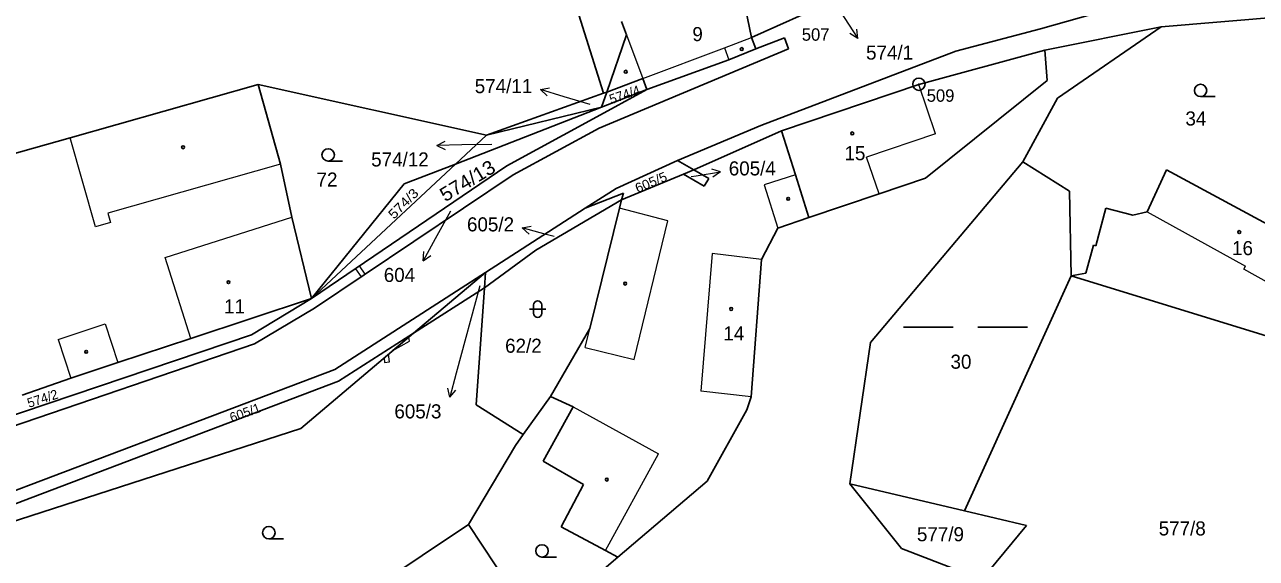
# Model space of a CAD drawing. Extents: x -664548 to -662415, y -1069720 to -1068208.
# Drawn here: x -663758.5 to -663609.5, y -1068970.2 to -1068905.8 of the extents above; entities that cross this region are included whole.
import ezdxf
from ezdxf.enums import TextEntityAlignment as Align

# ---------------------------------------------------------------- set-up
doc = ezdxf.new("R2010")
doc.units = 0
doc.header["$LTSCALE"] = 0.68
for name, color, linetype, lineweight in [('1', 7, 'Continuous', 25), ('13', 7, 'Continuous', 13), ('3', 7, 'Continuous', 25), ('4', 7, 'Continuous', 13), ('5', 7, 'Continuous', 25), ('7', 7, 'Continuous', 13), ('8', 7, 'Continuous', 25)]:
    doc.layers.add(name, color=color, linetype=linetype, lineweight=lineweight)
doc.layers.add('2', color=7, linetype='Continuous')

msp = doc.modelspace()

# ---------------------------------------------------------------- linework, layer by layer
at = {"layer": '1'}
for p, q in [((-663688.48, -1068914.05), (-663694.97, -1068893.3)), ((-663670.58, -1068907.33), (-663672.05, -1068900.05)), ((-663661.03, -1068903.04), (-663670.58, -1068907.33)), ((-663635.63, -1068906.27), (-663624.91, -1068903.24)), ((-663686.3, -1068905.38), (-663685.7, -1068906.99)), ((-663621.07, -1068906.02), (-663605.87, -1068904.77)), ((-663688.09, -1068913.91), (-663685.7, -1068906.99)), ((-663645.87, -1068908.98), (-663635.63, -1068906.27)), ((-663635.13, -1068908.83), (-663621.07, -1068906.02)), ((-663633.59, -1068914.64), (-663621.07, -1068906.02)), ((-663670.58, -1068907.33), (-663670.07, -1068908.7)), ((-663666.61, -1068907.36), (-663670.07, -1068908.7)), ((-663666.12, -1068908.69), (-663666.61, -1068907.36)), ((-663666.12, -1068908.69), (-663688.99, -1068918.26)), ((-663673.32, -1068910.01), (-663683.22, -1068913.6)), ((-663670.07, -1068908.7), (-663673.32, -1068910.01)), ((-663669.47, -1068917.93), (-663645.87, -1068908.98)), ((-663650.34, -1068913.01), (-663635.13, -1068908.83)), ((-663634.85, -1068912.51), (-663635.13, -1068908.83)), ((-663752.94, -1068919.42), (-663730.23, -1068912.99)), ((-663727.51, -1068922.61), (-663730.23, -1068912.99)), ((-663730.23, -1068912.99), (-663702.63, -1068919.1)), ((-663688.09, -1068913.91), (-663683.73, -1068912.25)), ((-663683.22, -1068913.6), (-663683.73, -1068912.25)), ((-663650.34, -1068913.01), (-663666.94, -1068918.58)), ((-663634.85, -1068912.51), (-663649.56, -1068924.31)), ((-663702.63, -1068919.1), (-663688.48, -1068914.05)), ((-663689.73, -1068917.14), (-663683.22, -1068913.6)), ((-663683.22, -1068913.6), (-663688.72, -1068915.74)), ((-663688.72, -1068915.74), (-663688.09, -1068913.91)), ((-663688.48, -1068914.05), (-663688.09, -1068913.91)), ((-663688.72, -1068915.74), (-663706.38, -1068922.6)), ((-663688.72, -1068915.74), (-663702.63, -1068919.1)), ((-663637.77, -1068922.34), (-663633.59, -1068914.64)), ((-663700.15, -1068922.8), (-663689.73, -1068917.14)), ((-663688.99, -1068918.26), (-663699.4, -1068923.92)), ((-663679.51, -1068922.17), (-663669.47, -1068917.93)), ((-663677.57, -1068923.28), (-663666.94, -1068918.58)), ((-663666.94, -1068918.58), (-663665.25, -1068923.92)), ((-663762.84, -1068922.22), (-663752.94, -1068919.42)), ((-663706.38, -1068922.6), (-663702.63, -1068919.1)), ((-663726.17, -1068929.03), (-663727.51, -1068922.61)), ((-663723.79, -1068938.86), (-663706.38, -1068922.6)), ((-663723.79, -1068938.86), (-663700.15, -1068922.8)), ((-663712.56, -1068925), (-663706.38, -1068922.6)), ((-663686.95, -1068925.55), (-663679.51, -1068922.17)), ((-663677.57, -1068923.28), (-663679.51, -1068922.17)), ((-663678.82, -1068923.83), (-663677.57, -1068923.28)), ((-663675.74, -1068924.33), (-663677.57, -1068923.28)), ((-663656.19, -1068944.16), (-663637.77, -1068922.34)), ((-663637.77, -1068922.34), (-663632.15, -1068925.87)), ((-663620.39, -1068923.28), (-663622.73, -1068928.37)), ((-663600.3, -1068934.16), (-663620.39, -1068923.28)), ((-663712.56, -1068925), (-663723.79, -1068938.86)), ((-663699.4, -1068923.92), (-663723.41, -1068940)), ((-663686.29, -1068926.91), (-663678.82, -1068923.83)), ((-663676.31, -1068925.27), (-663678.82, -1068923.83)), ((-663675.74, -1068924.33), (-663676.31, -1068925.27)), ((-663665.25, -1068923.92), (-663663.63, -1068929.07)), ((-663649.56, -1068924.31), (-663655.16, -1068926.21)), ((-663686.95, -1068925.55), (-663690.69, -1068927.95)), ((-663686.06, -1068926.11), (-663690.69, -1068927.95)), ((-663686.06, -1068926.11), (-663686.29, -1068926.91)), ((-663655.16, -1068926.21), (-663663.63, -1068929.07)), ((-663632.15, -1068925.87), (-663631.94, -1068936.09)), ((-663690.69, -1068927.95), (-663702.75, -1068935.7)), ((-663696.64, -1068932.99), (-663686.29, -1068926.91)), ((-663690.13, -1068942.48), (-663686.53, -1068927.93)), ((-663686.53, -1068927.93), (-663686.29, -1068926.91)), ((-663628.96, -1068932.46), (-663627.75, -1068927.91)), ((-663627.75, -1068927.91), (-663624.46, -1068928.78)), ((-663723.79, -1068938.86), (-663726.17, -1068929.03)), ((-663663.63, -1068929.07), (-663667.4, -1068930.35)), ((-663624.46, -1068928.78), (-663622.73, -1068928.37)), ((-663667.4, -1068930.35), (-663669.36, -1068934.13)), ((-663630.15, -1068935.78), (-663629.24, -1068932.38)), ((-663629.24, -1068932.38), (-663628.96, -1068932.46)), ((-663702.87, -1068937.55), (-663696.64, -1068932.99)), ((-663670.62, -1068950.72), (-663669.36, -1068934.13)), ((-663702.75, -1068935.7), (-663720.97, -1068947.42)), ((-663711.43, -1068943.03), (-663702.75, -1068935.7)), ((-663702.75, -1068935.7), (-663702.87, -1068937.55)), ((-663631.94, -1068936.09), (-663644.81, -1068964.51)), ((-663631.94, -1068936.09), (-663630.15, -1068935.78)), ((-663631.94, -1068936.09), (-663605.01, -1068944.41)), ((-663711.43, -1068943.03), (-663702.87, -1068937.55)), ((-663702.87, -1068937.55), (-663703.87, -1068951.68)), ((-663738.37, -1068943.66), (-663723.79, -1068938.86)), ((-663723.79, -1068938.86), (-663731.04, -1068943.25)), ((-663723.41, -1068940), (-663730.69, -1068944.3)), ((-663694.89, -1068950.66), (-663690.13, -1068942.48)), ((-663783.89, -1068961.01), (-663731.04, -1068943.25)), ((-663783.45, -1068962.35), (-663730.69, -1068944.3)), ((-663747.18, -1068946.57), (-663738.37, -1068943.66)), ((-663725.06, -1068954.55), (-663711.43, -1068943.03)), ((-663711.43, -1068943.03), (-663720.5, -1068948.84)), ((-663658.71, -1068961.22), (-663656.19, -1068944.16)), ((-663752.88, -1068948.45), (-663747.18, -1068946.57)), ((-663720.97, -1068947.42), (-663768.1, -1068965.24)), ((-663720.5, -1068948.84), (-663767.57, -1068966.64)), ((-663752.88, -1068948.45), (-663758.76, -1068950.5)), ((-663703.87, -1068951.68), (-663698.18, -1068955.27)), ((-663698.18, -1068955.27), (-663694.89, -1068950.66)), ((-663694.89, -1068950.66), (-663692.14, -1068951.92)), ((-663671.15, -1068952.3), (-663670.62, -1068950.72)), ((-663692.14, -1068951.92), (-663695.76, -1068958.49)), ((-663675.95, -1068960.91), (-663671.15, -1068952.3)), ((-663772.74, -1068969.94), (-663725.06, -1068954.55)), ((-663699.11, -1068956.58), (-663698.18, -1068955.27)), ((-663704.81, -1068966.13), (-663699.11, -1068956.58)), ((-663690.91, -1068961.29), (-663695.76, -1068958.49)), ((-663690.91, -1068961.29), (-663693.59, -1068966.42)), ((-663686.76, -1068970.1), (-663675.95, -1068960.91)), ((-663652.45, -1068969.05), (-663658.71, -1068961.22)), ((-663658.71, -1068961.22), (-663644.81, -1068964.51)), ((-663644.81, -1068964.51), (-663637.34, -1068966.28)), ((-663704.81, -1068966.13), (-663748.36, -1068995.22)), ((-663696.63, -1068978.49), (-663704.81, -1068966.13)), ((-663693.59, -1068966.42), (-663688.24, -1068969.3)), ((-663637.34, -1068966.28), (-663642.72, -1068972.79)), ((-663686.76, -1068970.1), (-663688.24, -1068969.3)), ((-663642.72, -1068972.79), (-663652.45, -1068969.05)), ((-663696.63, -1068978.49), (-663686.76, -1068970.1))]:
    msp.add_line(p, q, dxfattribs=at)
at = {"layer": '13'}
for points in [[(-663717.77, -1068936.22), (-663717.27, -1068935.89), (-663717.97, -1068934.9), (-663718.46, -1068935.24)], [(-663712.01, -1068943.52), (-663713.93, -1068945.14), (-663711.94, -1068943.99)], [(-663714.35, -1068946.5), (-663714.45, -1068945.58), (-663715, -1068946.05), (-663714.94, -1068946.57)]]:
    msp.add_lwpolyline(points, close=True, dxfattribs=at)
at = {"layer": '3'}
for p, q in [((-663616.283, -1068914.46), (-663614.533, -1068914.46)), ((-663721.763, -1068922.25), (-663720.013, -1068922.25)), ((-663696.931, -1068939.621), (-663696.931, -1068940.622)), ((-663695.929, -1068940.622), (-663695.929, -1068939.621)), ((-663697.431, -1068940.121), (-663695.429, -1068940.121)), ((-663652.199, -1068942.31), (-663646.199, -1068942.31)), ((-663643.199, -1068942.31), (-663637.199, -1068942.31)), ((-663728.933, -1068967.88), (-663727.183, -1068967.88)), ((-663695.913, -1068970.08), (-663694.163, -1068970.08))]:
    msp.add_line(p, q, dxfattribs=at)
for centre in [(-663616.2829, -1068913.7098), (-663721.7629, -1068921.4998), (-663728.9329, -1068967.1298), (-663695.9129, -1068969.3298)]:
    msp.add_circle(centre, 0.75, dxfattribs=at)
for centre, start, end in [((-663696.43, -1068939.6209), 0, 180), ((-663696.43, -1068940.6209), 180, 359.98789)]:
    msp.add_arc(centre, 0.5, start, end, dxfattribs=at)
at = {"layer": '4'}
for p, q in [((-663685.7, -1068906.99), (-663683.73, -1068912.25)), ((-663683.73, -1068912.25), (-663673.86, -1068908.56)), ((-663673.86, -1068908.56), (-663670.58, -1068907.33)), ((-663673.86, -1068908.56), (-663673.32, -1068910.01)), ((-663648.35, -1068918.96), (-663650.34, -1068913.01)), ((-663648.35, -1068918.96), (-663656.66, -1068921.78)), ((-663749.89, -1068930.19), (-663752.94, -1068919.42)), ((-663655.16, -1068926.21), (-663656.66, -1068921.78)), ((-663727.51, -1068922.61), (-663748.39, -1068928.52)), ((-663680.69, -1068929.47), (-663686.53, -1068927.93)), ((-663748.39, -1068928.52), (-663748.06, -1068929.68)), ((-663741.48, -1068933.89), (-663726.17, -1068929.03)), ((-663622.73, -1068928.37), (-663610.86, -1068934.93)), ((-663748.06, -1068929.68), (-663749.89, -1068930.19)), ((-663738.37, -1068943.66), (-663741.48, -1068933.89)), ((-663675.33, -1068933.4), (-663676.69, -1068950.03)), ((-663669.36, -1068934.13), (-663675.33, -1068933.4)), ((-663611.07, -1068935.31), (-663610.86, -1068934.93)), ((-663602.92, -1068939.87), (-663611.07, -1068935.31)), ((-663754.42, -1068943.8), (-663748.72, -1068941.91)), ((-663748.72, -1068941.91), (-663747.18, -1068946.57)), ((-663690.7, -1068944.77), (-663690.13, -1068942.48)), ((-663754.42, -1068943.8), (-663752.88, -1068948.45)), ((-663670.62, -1068950.72), (-663676.69, -1068950.03)), ((-663692.14, -1068951.92), (-663681.81, -1068957.61)), ((-663688.24, -1068969.3), (-663681.81, -1068957.61))]:
    msp.add_line(p, q, dxfattribs=at)
for points in [[(-663665.25, -1068923.92), (-663669.05, -1068925.12), (-663667.4, -1068930.35)], [(-663690.7, -1068944.77), (-663684.75, -1068946.23), (-663680.69, -1068929.47)]]:
    msp.add_lwpolyline(points, dxfattribs=at)
at = {"layer": '5'}
for centre in [(-663671.7568, -1068908.7092), (-663685.7868, -1068911.4492), (-663658.3968, -1068918.8992), (-663739.3068, -1068920.5692), (-663666.1468, -1068926.7992), (-663611.6068, -1068930.8192), (-663733.8168, -1068936.8692), (-663685.8568, -1068937.0392), (-663673.0368, -1068940.1092), (-663751.0168, -1068945.2892), (-663688.0768, -1068960.7192)]:
    msp.add_circle(centre, 0.175, dxfattribs=at)
at = {"layer": '7'}
for p, q in [((-663657.726, -1068907.417), (-663657.851, -1068906.304)), ((-663696.09, -1068913.593), (-663695.279, -1068914.364)), ((-663708.611, -1068920.342), (-663707.6, -1068920.826)), ((-663674.326, -1068923.551), (-663675.393, -1068923.213)), ((-663698.299, -1068930.323), (-663697.461, -1068931.066)), ((-663710.265, -1068934.275), (-663709.341, -1068933.642)), ((-663707.057, -1068950.759), (-663706.314, -1068949.921))]:
    msp.add_line(p, q, dxfattribs=at)
for points in [[(-663660.18, -1068903.64), (-663659.36, -1068904.9), (-663657.726, -1068907.417), (-663658.691, -1068906.85)], [(-663690.09, -1068915.4), (-663693.22, -1068914.47), (-663696.09, -1068913.593), (-663694.986, -1068913.407)], [(-663701.98, -1068920.25), (-663705.61, -1068920.29), (-663708.611, -1068920.342), (-663707.618, -1068919.824)], [(-663677.89, -1068924.11), (-663677.29, -1068924.02), (-663674.326, -1068923.551), (-663675.237, -1068924.202)], [(-663706.98, -1068928.3), (-663708.81, -1068931.65), (-663710.265, -1068934.275), (-663710.217, -1068933.156)], [(-663694.44, -1068931.36), (-663695.4, -1068931.1), (-663698.299, -1068930.323), (-663697.202, -1068930.099)], [(-663703.42, -1068937.3), (-663706.28, -1068947.86), (-663707.057, -1068950.759), (-663707.281, -1068949.662)]]:
    msp.add_lwpolyline(points, dxfattribs=at)
at = {"layer": '8'}
for radius in [0.75, 0.03]:
    msp.add_circle((-663650.34, -1068912.9598), radius, dxfattribs=at)

# ---------------------------------------------------------------- texts
at = {"layer": '2'}
for s, p in [('9', (-663677.73, -1068907.755)), ('574/1', (-663656.73, -1068909.985)), ('34', (-663618.12, -1068917.945)), ('15', (-663659.34, -1068922.135)), ('605/4', (-663673.33, -1068923.975)), ('72', (-663723.17, -1068925.324)), ('16', (-663612.48, -1068933.604)), ('11', (-663734.35, -1068940.645)), ('14', (-663673.98, -1068943.905)), ('62/2', (-663700.37, -1068945.395)), ('30', (-663646.52, -1068947.324)), ('577/9', (-663650.58, -1068968.165)), ('577/8', (-663621.35, -1068967.465))]:
    msp.add_text(s, height=1.7, dxfattribs=at).set_placement(p)
for s, p in [('574/11', (-663697.089, -1068914.035)), ('574/12', (-663709.609, -1068922.895)), ('605/2', (-663699.29, -1068930.735)), ('604', (-663711.249, -1068936.845)), ('605/3', (-663708.07, -1068953.325))]:
    msp.add_text(s, height=1.7, dxfattribs=at).set_placement(p, align=Align.RIGHT)
for s, rotation, p in [('574/4', 19, (-663687.537, -1068915.369)), ('574/2', 18, (-663757.931, -1068952.061)), ('605/1', 20, (-663733.412, -1068953.817))]:
    msp.add_text(s, height=1.14, rotation=rotation, dxfattribs=at).set_placement(p)
for s, height, rotation, width, p in [('574/13', 1.7, 31, 1.05, (-663707.611, -1068927.224)), ('605/5', 1.14, 23, 1.05, (-663684.348, -1068926.112)), ('574/3', 1.14, 45, 1.15, (-663713.818, -1068929.331))]:
    msp.add_text(s, height=height, rotation=rotation, dxfattribs=dict(at, width=width)).set_placement(p)
at = {"layer": '8'}
for s, p in [('507', (-663661.152, -1068907.703)), ('509', (-663646.049, -1068915.077))]:
    msp.add_text(s, height=1.5, dxfattribs=at).set_placement(p, align=Align.RIGHT)

doc.saveas('drawing.dxf')
